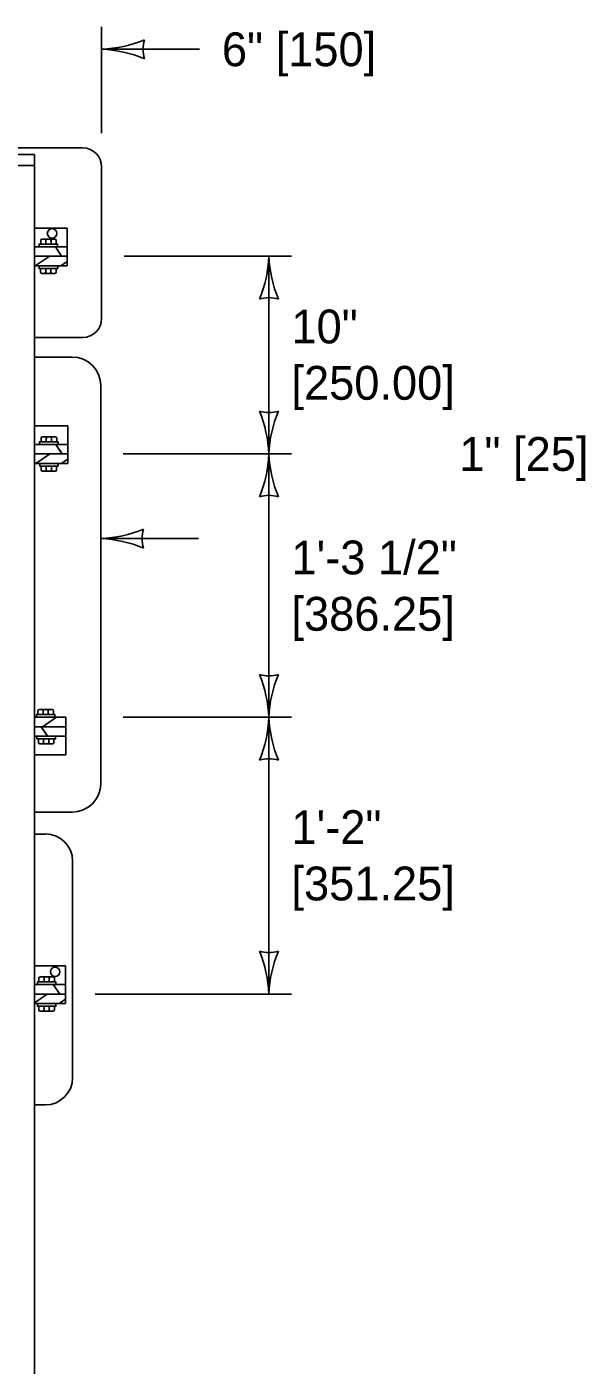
# Model space of a CAD drawing. Extents: x 49991.4 to 50021, y 49987.6 to 50011.4.
# Drawn here: x 50002.239 to 50003.23, y 49989.927 to 49992.302 of the extents above; entities that cross this region are included whole.
import ezdxf

# ---------------------------------------------------------------- set-up
doc = ezdxf.new("R2010")
doc.units = 0
for name, color, linetype in [('Level 1', 7, 'Continuous'), ('Level 2', 7, 'Continuous'), ('Level 3', 7, 'Continuous')]:
    doc.layers.add(name, color=color, linetype=linetype)

msp = doc.modelspace()

# ---------------------------------------------------------------- linework, layer by layer
at = {"layer": 'Level 1'}
for p, q in [((50001.5964, 49992.0873), (50002.3382, 49992.0873)), ((50002.192, 49992.0757), (50002.2528, 49992.0757)), ((50002.2528, 49992.0757), (50002.2527, 49988.4948)), ((50002.1922, 49992.0562), (50002.2532, 49992.0562)), ((50002.3719, 49992.0537), (50002.3719, 49991.7845)), ((50002.3108, 49991.9449), (50002.2528, 49991.9449)), ((50002.2661, 49991.9255), (50002.2889, 49991.9255)), ((50002.2662, 49991.9255), (50002.2889, 49991.9255)), ((50002.2728, 49991.9255), (50002.2728, 49991.9167)), ((50002.2821, 49991.9255), (50002.2821, 49991.9167)), ((50002.3108, 49991.8782), (50002.3108, 49991.9449)), ((50002.3108, 49991.9117), (50002.2528, 49991.9117)), ((50002.2637, 49991.9229), (50002.2637, 49991.9167)), ((50002.2897, 49991.9115), (50002.3008, 49991.895)), ((50002.2897, 49991.9115), (50002.2998, 49991.8965)), ((50002.2897, 49991.9115), (50002.2998, 49991.8965)), ((50002.2913, 49991.9229), (50002.2913, 49991.9167)), ((50002.3108, 49991.895), (50002.2528, 49991.895)), ((50002.3108, 49991.8782), (50002.2528, 49991.8782)), ((50002.2541, 49991.8782), (50002.2785, 49991.8948)), ((50002.3108, 49991.895), (50002.2558, 49991.895)), ((50002.3108, 49991.895), (50002.2558, 49991.895)), ((50002.3108, 49991.895), (50002.2571, 49991.895)), ((50002.2994, 49991.8782), (50002.3108, 49991.8859)), ((50002.2635, 49991.8669), (50002.2635, 49991.8731)), ((50002.2886, 49991.8644), (50002.266, 49991.8644)), ((50002.2887, 49991.8644), (50002.266, 49991.8644)), ((50002.2727, 49991.8644), (50002.2727, 49991.8731)), ((50002.282, 49991.8644), (50002.282, 49991.8731)), ((50002.2911, 49991.8669), (50002.2911, 49991.8731)), ((50002.3382, 49991.7509), (50002.2528, 49991.7508)), ((50002.3197, 49991.7161), (50002.2528, 49991.7161)), ((50002.3702, 49990.959), (50002.3702, 49991.6656)), ((50002.3117, 49991.5942), (50002.2532, 49991.5942)), ((50002.3117, 49991.5275), (50002.3117, 49991.5942)), ((50002.2645, 49991.5722), (50002.2645, 49991.566)), ((50002.267, 49991.5747), (50002.2897, 49991.5747)), ((50002.2671, 49991.5747), (50002.2897, 49991.5747)), ((50002.2737, 49991.5747), (50002.2737, 49991.566)), ((50002.283, 49991.5747), (50002.283, 49991.566)), ((50002.2922, 49991.5722), (50002.2922, 49991.566)), ((50002.3117, 49991.5609), (50002.2528, 49991.5609)), ((50002.2906, 49991.5608), (50002.3016, 49991.5442)), ((50002.2906, 49991.5608), (50002.3006, 49991.5457)), ((50002.2906, 49991.5608), (50002.3006, 49991.5457)), ((50002.3117, 49991.5442), (50002.2528, 49991.5442)), ((50002.3117, 49991.5275), (50002.2528, 49991.5275)), ((50002.255, 49991.5275), (50002.2793, 49991.544)), ((50002.3117, 49991.5442), (50002.2566, 49991.5442)), ((50002.3117, 49991.5442), (50002.2566, 49991.5442)), ((50002.3117, 49991.5442), (50002.258, 49991.5442)), ((50002.2643, 49991.5162), (50002.2643, 49991.5224)), ((50002.2736, 49991.5136), (50002.2736, 49991.5224)), ((50002.2829, 49991.5136), (50002.2829, 49991.5224)), ((50002.292, 49991.5162), (50002.292, 49991.5224)), ((50002.3002, 49991.5275), (50002.3117, 49991.5351)), ((50002.2894, 49991.5136), (50002.2668, 49991.5136)), ((50002.2895, 49991.5136), (50002.2668, 49991.5136)), ((50002.2528, 49991.0768), (50002.3081, 49991.0768)), ((50002.2587, 49991.088), (50002.2587, 49991.0819)), ((50002.2612, 49991.0906), (50002.2839, 49991.0906)), ((50002.2613, 49991.0906), (50002.2839, 49991.0906)), ((50002.292, 49991.0769), (50002.2672, 49991.0601)), ((50002.2679, 49991.0906), (50002.2679, 49991.0819)), ((50002.2772, 49991.0906), (50002.2772, 49991.0819)), ((50002.2864, 49991.088), (50002.2864, 49991.0819)), ((50002.3081, 49991.0101), (50002.3081, 49991.0768)), ((50002.2528, 49991.0601), (50002.307, 49991.0601)), ((50002.2537, 49991.0601), (50002.307, 49991.0601)), ((50002.2537, 49991.0601), (50002.307, 49991.0601)), ((50002.2537, 49991.0601), (50002.3059, 49991.0601)), ((50002.2645, 49991.0601), (50002.2759, 49991.0434)), ((50002.2645, 49991.0601), (50002.2755, 49991.044)), ((50002.2645, 49991.0601), (50002.2755, 49991.044)), ((50002.2528, 49991.0434), (50002.307, 49991.0434)), ((50002.2537, 49991.0434), (50002.3081, 49991.0434)), ((50002.2596, 49991.0322), (50002.2596, 49991.0383)), ((50002.2847, 49991.0296), (50002.2621, 49991.0296)), ((50002.2848, 49991.0296), (50002.2621, 49991.0296)), ((50002.2688, 49991.0296), (50002.2688, 49991.0383)), ((50002.2781, 49991.0296), (50002.2781, 49991.0383)), ((50002.2872, 49991.0322), (50002.2872, 49991.0383)), ((50002.2528, 49991.0101), (50002.3081, 49991.0101)), ((50002.2528, 49990.9086), (50002.3197, 49990.9086)), ((50002.2528, 49990.8697), (50002.2722, 49990.8697)), ((50002.3202, 49990.8216), (50002.3202, 49990.4372)), ((50002.3077, 49990.6357), (50002.2535, 49990.6357)), ((50002.3077, 49990.5691), (50002.3077, 49990.6357)), ((50002.3077, 49990.6025), (50002.2528, 49990.6025)), ((50002.2605, 49990.6137), (50002.2605, 49990.6075)), ((50002.263, 49990.6163), (50002.2857, 49990.6163)), ((50002.2631, 49990.6163), (50002.2857, 49990.6163)), ((50002.2697, 49990.6163), (50002.2697, 49990.6075)), ((50002.279, 49990.6163), (50002.279, 49990.6075)), ((50002.2866, 49990.6023), (50002.2976, 49990.5858)), ((50002.2866, 49990.6023), (50002.2966, 49990.5873)), ((50002.2866, 49990.6023), (50002.2966, 49990.5873)), ((50002.2882, 49990.6137), (50002.2882, 49990.6075)), ((50002.3077, 49990.5858), (50002.2527, 49990.5858)), ((50002.3077, 49990.5858), (50002.2527, 49990.5858)), ((50002.3077, 49990.5858), (50002.2527, 49990.5858)), ((50002.2528, 49990.5703), (50002.2754, 49990.5856)), ((50002.3077, 49990.5858), (50002.254, 49990.5858)), ((50002.2968, 49990.5694), (50002.3077, 49990.5767)), ((50002.3077, 49990.5691), (50002.2528, 49990.5691)), ((50002.2603, 49990.5577), (50002.2603, 49990.5639)), ((50002.2854, 49990.5552), (50002.2628, 49990.5552)), ((50002.2855, 49990.5552), (50002.2628, 49990.5552)), ((50002.2696, 49990.5552), (50002.2696, 49990.5639)), ((50002.2789, 49990.5552), (50002.2789, 49990.5639)), ((50002.288, 49990.5577), (50002.288, 49990.5639)), ((50002.2722, 49990.3891), (50002.2528, 49990.3891))]:
    msp.add_line(p, q, dxfattribs=at)
for points in [[(50002.2609, 49991.9119), (50002.2609, 49991.9165), (50002.2938, 49991.9165), (50002.2938, 49991.9119)], [(50002.2939, 49991.878), (50002.2939, 49991.8733), (50002.261, 49991.8733), (50002.261, 49991.878)], [(50002.2618, 49991.5611), (50002.2618, 49991.5658), (50002.2946, 49991.5658), (50002.2946, 49991.5611)], [(50002.2947, 49991.5272), (50002.2947, 49991.5226), (50002.2619, 49991.5226), (50002.2619, 49991.5272)], [(50002.256, 49991.077), (50002.256, 49991.0817), (50002.2889, 49991.0817), (50002.2889, 49991.077)], [(50002.29, 49991.0432), (50002.29, 49991.0385), (50002.2571, 49991.0385), (50002.2571, 49991.0432)], [(50002.2578, 49990.6027), (50002.2578, 49990.6073), (50002.2907, 49990.6073), (50002.2907, 49990.6027)], [(50002.2907, 49990.5688), (50002.2907, 49990.5641), (50002.2579, 49990.5641), (50002.2579, 49990.5688)]]:
    msp.add_lwpolyline(points, close=True, dxfattribs=at)
for centre in [(50002.2839, 49991.9356), (50002.2893, 49990.6252)]:
    msp.add_circle(centre, 0.00843, dxfattribs=at)
for centre, radius, start, end in [((50002.3382, 49992.0537), 0.0336, 0, 90), ((50002.2663, 49991.9229), 0.00257, 90, 180), ((50002.2703, 49991.9229), 0.00257, 0, 90), ((50002.2755, 49991.9229), 0.00257, 90, 180), ((50002.2795, 49991.9229), 0.00257, 0, 90), ((50002.2847, 49991.9229), 0.00257, 90, 180), ((50002.2887, 49991.9229), 0.00257, 0, 90), ((50002.2661, 49991.8669), 0.00257, 180, 270), ((50002.2701, 49991.8669), 0.00257, 270, 0), ((50002.2753, 49991.8669), 0.00257, 180, 270), ((50002.2793, 49991.8669), 0.00257, 270, 0), ((50002.2845, 49991.8669), 0.00257, 180, 270), ((50002.2885, 49991.8669), 0.00257, 270, 0), ((50002.3382, 49991.7845), 0.0336, 270, 0), ((50002.3197, 49991.6656), 0.0505, 0, 90), ((50002.2671, 49991.5722), 0.00257, 90, 180), ((50002.2712, 49991.5722), 0.00257, 0, 90), ((50002.2763, 49991.5722), 0.00257, 90, 180), ((50002.2804, 49991.5722), 0.00257, 0, 90), ((50002.2855, 49991.5722), 0.00257, 90, 180), ((50002.2896, 49991.5722), 0.00257, 0, 90), ((50002.2669, 49991.5162), 0.00257, 180, 270), ((50002.271, 49991.5162), 0.00257, 270, 0), ((50002.2761, 49991.5162), 0.00257, 180, 270), ((50002.2802, 49991.5162), 0.00257, 270, 0), ((50002.2853, 49991.5162), 0.00257, 180, 270), ((50002.2894, 49991.5162), 0.00257, 270, 0), ((50002.2613, 49991.0881), 0.00257, 90, 180), ((50002.2654, 49991.0881), 0.00257, 0, 90), ((50002.2705, 49991.0881), 0.00257, 90, 180), ((50002.2746, 49991.0881), 0.00257, 0, 90), ((50002.2797, 49991.0881), 0.00257, 90, 180), ((50002.2838, 49991.0881), 0.00257, 0, 90), ((50002.2622, 49991.0321), 0.00257, 180, 270), ((50002.2662, 49991.0321), 0.00257, 270, 0), ((50002.2714, 49991.0321), 0.00257, 180, 270), ((50002.2754, 49991.0321), 0.00257, 270, 0), ((50002.2806, 49991.0321), 0.00257, 180, 270), ((50002.2846, 49991.0321), 0.00257, 270, 0), ((50002.3197, 49990.959), 0.0505, 270, 0), ((50002.2722, 49990.8217), 0.0481, 0, 90), ((50002.2631, 49990.6137), 0.00257, 90, 180), ((50002.2672, 49990.6137), 0.00257, 0, 90), ((50002.2723, 49990.6137), 0.00257, 90, 180), ((50002.2764, 49990.6137), 0.00257, 0, 90), ((50002.2815, 49990.6137), 0.00257, 90, 180), ((50002.2856, 49990.6137), 0.00257, 0, 90), ((50002.2629, 49990.5577), 0.00257, 180, 270), ((50002.267, 49990.5577), 0.00257, 270, 0), ((50002.2721, 49990.5577), 0.00257, 180, 270), ((50002.2762, 49990.5577), 0.00257, 270, 0), ((50002.2813, 49990.5577), 0.00257, 180, 270), ((50002.2854, 49990.5577), 0.00257, 270, 0), ((50002.2722, 49990.4371), 0.0481, 270, 0)]:
    msp.add_arc(centre, radius, start, end, dxfattribs=at)
at = {"layer": 'Level 3'}
for p, q in [((50002.3719, 49992.3023), (50002.3719, 49992.1137)), ((50002.3719, 49992.2623), (50002.5453, 49992.2623)), ((50002.4119, 49991.895), (50002.7087, 49991.895)), ((50002.6687, 49991.5442), (50002.6687, 49991.895)), ((50002.4102, 49991.5442), (50002.7087, 49991.5442)), ((50002.6687, 49991.5442), (50002.6687, 49991.0768)), ((50002.3702, 49991.394), (50002.5436, 49991.394)), ((50002.4102, 49991.0768), (50002.7087, 49991.0768)), ((50002.6687, 49991.0768), (50002.6687, 49990.5858)), ((50002.3602, 49990.5858), (50002.7087, 49990.5858))]:
    msp.add_line(p, q, dxfattribs=at)
for centre, radius, start, end in [((50002.3604, 49992.495), 0.233, 272.8273, 292.0772), ((50002.3627, 49992.0402), 0.2223, 67.456, 87.6395), ((50002.5001, 49992.2623), 0.0548, 162.1388, 197.8612), ((50002.4466, 49991.9042), 0.2223, 337.456, 357.6395), ((50002.9014, 49991.9065), 0.233, 182.8273, 202.0772), ((50002.6687, 49991.7668), 0.0548, 72.1388, 107.8612), ((50002.6687, 49991.6724), 0.0548, 252.1388, 287.8612), ((50002.436, 49991.5327), 0.233, 2.8273, 22.0772), ((50002.8908, 49991.535), 0.2223, 157.456, 177.6395), ((50002.4466, 49991.5534), 0.2223, 337.456, 357.6395), ((50002.9014, 49991.5557), 0.233, 182.8273, 202.0772), ((50002.6687, 49991.416), 0.0548, 72.1388, 107.8612), ((50002.3587, 49991.6267), 0.233, 272.8273, 292.0772), ((50002.4984, 49991.394), 0.0548, 162.1388, 197.8612), ((50002.361, 49991.1719), 0.2223, 67.456, 87.6395), ((50002.6687, 49991.205), 0.0548, 252.1388, 287.8612), ((50002.436, 49991.0653), 0.233, 2.8273, 22.0772), ((50002.8908, 49991.0676), 0.2223, 157.456, 177.6395), ((50002.4466, 49991.086), 0.2223, 337.456, 357.6395), ((50002.9014, 49991.0883), 0.233, 182.8273, 202.0772), ((50002.6687, 49990.9486), 0.0548, 72.1388, 107.8612), ((50002.6687, 49990.714), 0.0548, 252.1388, 287.8612), ((50002.436, 49990.5743), 0.233, 2.8273, 22.0772), ((50002.8908, 49990.5766), 0.2223, 157.456, 177.6395)]:
    msp.add_arc(centre, radius, start, end, dxfattribs=at)

# ---------------------------------------------------------------- texts
at = {"layer": 'Level 2'}
for s, p in [('6" [150]', (50002.5853, 49992.2323)), ('10"', (50002.7087, 49991.7404)), ('[250.00]', (50002.7087, 49991.6404)), ('1" [25]', (50003.0066, 49991.5142)), ('1\'-3 1/2"', (50002.7087, 49991.3305)), ('[386.25]', (50002.7087, 49991.2305)), ('1\'-2"', (50002.7087, 49990.8519)), ('[351.25]', (50002.7087, 49990.7519))]:
    msp.add_text(s, height=0.06, dxfattribs=at).set_placement(p)

doc.saveas('drawing.dxf')
